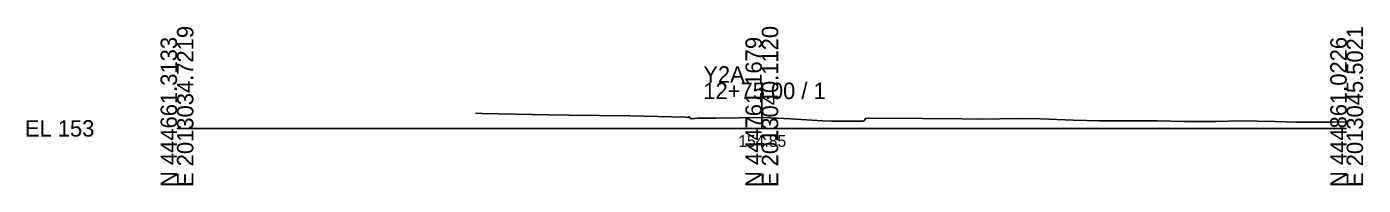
# Model space of a CAD drawing. Extents: x -26 to 203, y -10 to 5517.
# Drawn here: x -25.7 to 202.8, y 5490.3 to 5517.3 of the extents above; entities that cross this region are included whole.
import ezdxf

# ---------------------------------------------------------------- set-up
doc = ezdxf.new("R2010")
doc.units = 0
for name, color, linetype in [('Default', 7, 'Continuous'), ('Exist Cross Section Cell', 7, 'Continuous'), ('Exist XS Center Line Elevation Label', 7, 'Continuous'), ('Exist XS Ground Line', 7, 'Continuous')]:
    doc.layers.add(name, color=color, linetype=linetype)

msp = doc.modelspace()

# ---------------------------------------------------------------- linework, layer by layer
at = {"layer": 'Exist Cross Section Cell'}
for p, q in [((100, 5500), (100, 5507.81)), ((0, 5500), (100, 5500)), ((100, 5500), (200, 5500))]:
    msp.add_line(p, q, dxfattribs=at)
at = {"layer": 'Exist XS Ground Line'}
msp.add_lwpolyline([(51.03, 5502.6), (52.16, 5502.53), (63.58, 5502.33), (67, 5502.27), (77.5, 5502.14), (86.9, 5501.89), (87.48, 5501.86), (87.54, 5502), (87.92, 5501.65), (89.06, 5501.72), (89.5, 5501.74), (92.18, 5501.76), (100, 5501.85), (100.36, 5501.85), (104.89, 5501.65), (110.37, 5501.3), (111.94, 5501.21), (116.31, 5501.21), (117.38, 5501.24), (117.77, 5501.71), (118.3, 5501.72), (127.6, 5501.69), (134.28, 5501.64), (137.61, 5501.58), (143.79, 5501.69), (147.63, 5501.64), (153.29, 5501.38), (157.65, 5501.27), (162.79, 5501.31), (167.66, 5501.32), (172.29, 5501.2), (177.68, 5501.16), (181.8, 5501.3), (187.69, 5501.19), (191.3, 5501.07), (197.71, 5501.09), (200, 5501.11)], dxfattribs=at)

# ---------------------------------------------------------------- texts
at = {"layer": 'Default'}
msp.add_text('-', height=0.0001, dxfattribs=at).set_placement((0, 5500))
at = {"layer": 'Exist Cross Section Cell'}
for s, p in [('E 2013034.7219', (2.8, 5490)), ('E 2013040.1120', (102.8, 5490)), ('E 2013045.5021', (202.8, 5490)), ('N 444661.3133', (0, 5490)), ('N 444761.1679', (100, 5490)), ('N 444861.0226', (200, 5490))]:
    msp.add_text(s, height=2.8, rotation=90, dxfattribs=at).set_placement(p)
for s, p in [('Y2A', (90, 5507.81)), ('12+75.00 / 1', (90, 5505.01)), ('EL 153', (-26, 5498.6))]:
    msp.add_text(s, height=2.8, dxfattribs=at).set_placement(p)
at = {"layer": 'Exist XS Center Line Elevation Label'}
msp.add_text('154.85', height=2, dxfattribs=at).set_placement((95.98, 5496.85))

doc.saveas('drawing.dxf')
